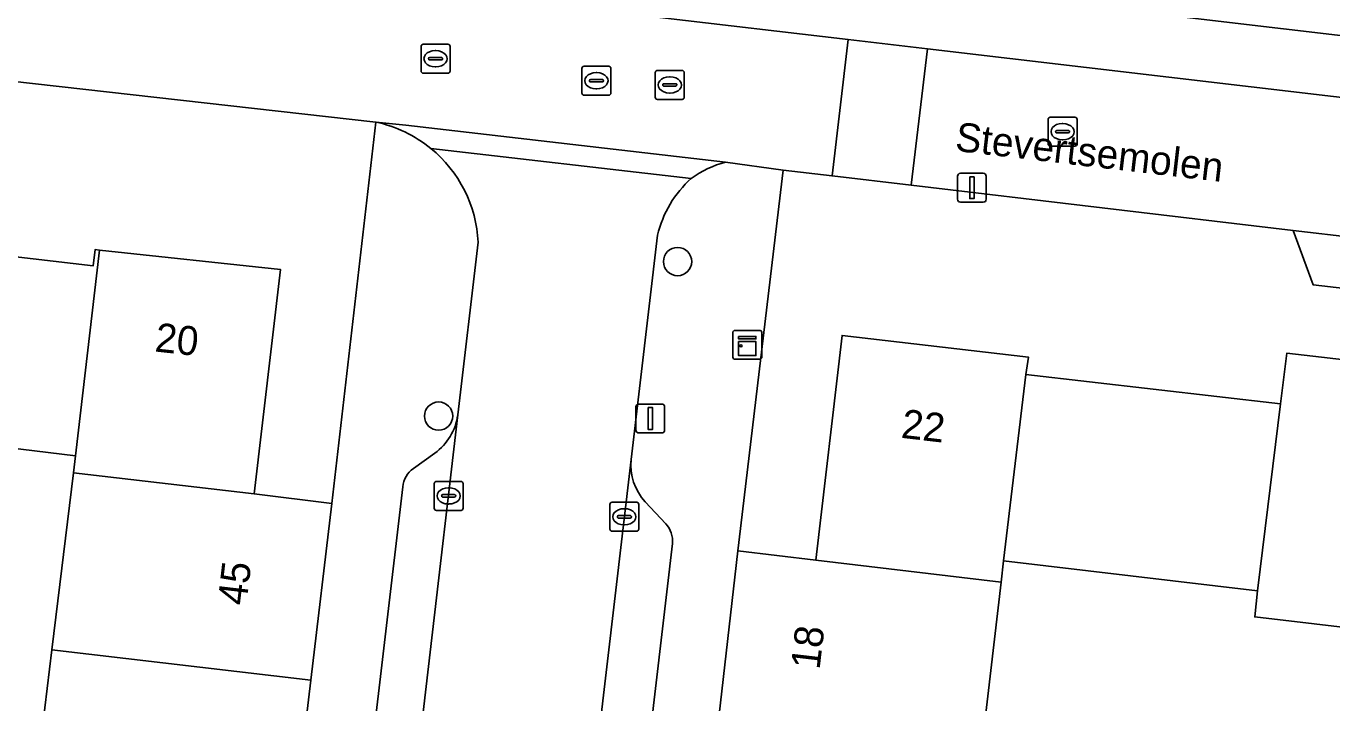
# Model space of a CAD drawing. Extents: x 161241 to 161758, y 384138 to 384885.
# Drawn here: x 161373.53 to 161418.62, y 384405.84 to 384429.23 of the extents above; entities that cross this region are included whole.
import ezdxf

# ---------------------------------------------------------------- set-up
doc = ezdxf.new("R2010")
doc.units = 0
for name, color, linetype in [('IMGEO_Boom', 7, 'Continuous'), ('IMGEO_Erf', 7, 'Continuous'), ('IMGEO_Groenvoorziening', 7, 'Continuous'), ('IMGEO_Kast', 7, 'Continuous'), ('IMGEO_Kolk', 7, 'Continuous'), ('IMGEO_Lichtmast', 7, 'Continuous'), ('IMGEO_Openbare_ruimte_label', 7, 'Continuous'), ('IMGEO_Pand', 7, 'Continuous'), ('IMGEO_Pand_nummerreeks', 7, 'Continuous'), ('IMGEO_Parkeervlak_open', 7, 'Continuous'), ('IMGEO_Rijbaan_lokaal_open', 7, 'Continuous'), ('IMGEO_Rioolput', 7, 'Continuous'), ('IMGEO_Voetpad_open', 7, 'Continuous')]:
    doc.layers.add(name, color=color, linetype=linetype)

msp = doc.modelspace()

# ---------------------------------------------------------------- linework, layer by layer
at = {"layer": 'IMGEO_Boom'}
for centre in [(161396.026, 384421.095), (161387.773, 384415.756)]:
    msp.add_circle(centre, 0.489, dxfattribs=at)
at = {"layer": 'IMGEO_Erf'}
for points in [[(161367.047, 384421.971), (161375.849, 384420.952), (161375.912, 384421.508), (161376.061, 384421.492), (161382.318, 384420.819), (161381.408, 384413.065), (161384.082, 384412.738), (161385.608, 384425.915), (161367.914, 384427.91)], [(161457.727, 384415.687), (161417.974, 384420.297), (161417.282, 384422.167), (161404.094, 384423.73), (161401.363, 384424.054), (161399.676, 384424.254), (161398.105, 384411.096), (161400.801, 384410.777), (161401.706, 384418.545), (161408.14, 384417.794), (161408.057, 384417.189), (161416.852, 384416.18), (161417.063, 384417.929), (161423.139, 384417.232)], [(161373.691, 384401.666), (161374.421, 384407.672), (161375.166, 384413.798), (161375.237, 384414.381), (161366.442, 384415.451)], [(161422.108, 384408.094), (161415.958, 384408.816), (161416.056, 384409.721), (161407.286, 384410.751), (161407.2, 384410.016), (161406.484, 384403.913), (161405.779, 384397.909), (161405.074, 384391.905), (161404.37, 384385.901), (161403.665, 384379.897), (161402.961, 384373.893), (161402.239, 384367.742), (161402.158, 384367.051), (161406.611, 384366.529), (161410.938, 384366.021), (161411.046, 384366.935), (161417.35, 384366.195), (161423.302, 384365.497)]]:
    msp.add_lwpolyline(points, dxfattribs=at)
at = {"layer": 'IMGEO_Groenvoorziening'}
msp.add_lwpolyline([(161409.377, 384462.778), (161397.9, 384454.084), (161411.738, 384445.455), (161410.62, 384434.912), (161410.092, 384429.939), (161427.439, 384427.904), (161432.833, 384473.658)], dxfattribs=at)
at = {"layer": 'IMGEO_Kast'}
for p, q in [((161398.01, 384418.718), (161398.851, 384418.718)), ((161398.851, 384418.718), (161398.01, 384418.718)), ((161397.935, 384417.793), (161397.935, 384418.634)), ((161397.935, 384418.634), (161397.935, 384417.793)), ((161398.935, 384418.643), (161398.935, 384417.802)), ((161398.935, 384417.802), (161398.935, 384418.643)), ((161398.86, 384417.718), (161398.019, 384417.718)), ((161398.019, 384417.718), (161398.86, 384417.718))]:
    msp.add_line(p, q, dxfattribs=at)
for points in [[(161398.13, 384418.508), (161398.73, 384418.508), (161398.73, 384418.423), (161398.13, 384418.423), (161398.13, 384418.508)], [(161398.13, 384418.333), (161398.73, 384418.333), (161398.73, 384417.844), (161398.13, 384417.844), (161398.13, 384418.333)]]:
    msp.add_lwpolyline(points, dxfattribs=at)
msp.add_circle((161398.214, 384418.182), 0.0377, dxfattribs=at)
for centre, start, end in [((161398.013, 384418.64), 92.4484, 184.2845), ((161398.013, 384418.64), 92.4484, 184.2845), ((161398.857, 384418.64), 2.4484, 94.2845), ((161398.857, 384418.64), 2.4484, 94.2845), ((161398.013, 384417.796), 182.4484, 274.2845), ((161398.013, 384417.796), 182.4484, 274.2845), ((161398.857, 384417.796), 272.4484, 4.2845), ((161398.857, 384417.796), 272.4484, 4.2845)]:
    msp.add_arc(centre, 0.0779, start, end, dxfattribs=at)
at = {"layer": 'IMGEO_Kolk'}
for p, q in [((161387.243, 384428.606), (161388.095, 384428.606)), ((161387.168, 384427.68), (161387.168, 384428.532)), ((161387.656, 384428.386), (161387.681, 384428.386)), ((161388.169, 384428.532), (161388.169, 384427.68)), ((161387.427, 384428.1), (161387.427, 384428.112)), ((161387.865, 384428.063), (161387.467, 384428.063)), ((161387.47, 384428.149), (161387.868, 384428.149)), ((161387.679, 384427.826), (161387.654, 384427.826)), ((161387.911, 384428.112), (161387.911, 384428.1)), ((161388.095, 384427.606), (161387.243, 384427.606)), ((161395.256, 384426.773), (161395.256, 384427.625)), ((161395.331, 384427.699), (161396.183, 384427.699)), ((161395.744, 384427.479), (161395.769, 384427.479)), ((161396.257, 384427.625), (161396.257, 384426.773)), ((161395.515, 384427.193), (161395.515, 384427.205)), ((161395.953, 384427.156), (161395.555, 384427.156)), ((161395.558, 384427.242), (161395.956, 384427.242)), ((161395.767, 384426.919), (161395.742, 384426.919)), ((161395.999, 384427.205), (161395.999, 384427.193)), ((161396.183, 384426.699), (161395.331, 384426.699)), ((161408.822, 384425.158), (161408.822, 384426.01)), ((161408.897, 384426.084), (161409.749, 384426.084)), ((161409.823, 384426.01), (161409.823, 384425.158)), ((161409.081, 384425.578), (161409.081, 384425.59)), ((161409.519, 384425.541), (161409.121, 384425.541)), ((161409.124, 384425.627), (161409.522, 384425.627)), ((161409.31, 384425.864), (161409.335, 384425.864)), ((161409.565, 384425.59), (161409.565, 384425.578)), ((161409.749, 384425.084), (161408.897, 384425.084)), ((161409.333, 384425.304), (161409.308, 384425.304)), ((161387.62, 384412.571), (161387.62, 384413.423)), ((161387.695, 384413.497), (161388.547, 384413.497)), ((161388.108, 384413.277), (161388.133, 384413.277)), ((161388.621, 384413.423), (161388.621, 384412.571)), ((161387.879, 384412.991), (161387.879, 384413.003)), ((161388.317, 384412.954), (161387.919, 384412.954)), ((161387.922, 384413.04), (161388.32, 384413.04)), ((161388.363, 384413.003), (161388.363, 384412.991)), ((161388.547, 384412.497), (161387.695, 384412.497)), ((161388.131, 384412.717), (161388.106, 384412.717)), ((161393.687, 384411.849), (161393.687, 384412.701)), ((161393.762, 384412.775), (161394.614, 384412.775)), ((161394.175, 384412.555), (161394.2, 384412.555)), ((161394.688, 384412.701), (161394.688, 384411.849)), ((161393.946, 384412.269), (161393.946, 384412.281)), ((161394.384, 384412.232), (161393.986, 384412.232)), ((161393.989, 384412.318), (161394.387, 384412.318)), ((161394.198, 384411.995), (161394.173, 384411.995)), ((161394.43, 384412.281), (161394.43, 384412.269)), ((161394.614, 384411.775), (161393.762, 384411.775))]:
    msp.add_line(p, q, dxfattribs=at)
for points in [[(161387.243, 384428.606), (161388.095, 384428.606)], [(161387.168, 384427.68), (161387.168, 384428.532)], [(161388.169, 384428.532), (161388.169, 384427.68)], [(161388.095, 384427.606), (161387.243, 384427.606)], [(161395.256, 384426.773), (161395.256, 384427.625)], [(161395.331, 384427.699), (161396.183, 384427.699)], [(161396.257, 384427.625), (161396.257, 384426.773)], [(161396.183, 384426.699), (161395.331, 384426.699)], [(161408.822, 384425.158), (161408.822, 384426.01)], [(161408.897, 384426.084), (161409.749, 384426.084)], [(161409.823, 384426.01), (161409.823, 384425.158)], [(161409.749, 384425.084), (161408.897, 384425.084)], [(161387.62, 384412.571), (161387.62, 384413.423)], [(161387.695, 384413.497), (161388.547, 384413.497)], [(161388.621, 384413.423), (161388.621, 384412.571)], [(161388.547, 384412.497), (161387.695, 384412.497)], [(161393.687, 384411.849), (161393.687, 384412.701)], [(161393.762, 384412.775), (161394.614, 384412.775)], [(161394.688, 384412.701), (161394.688, 384411.849)], [(161394.614, 384411.775), (161393.762, 384411.775)]]:
    msp.add_lwpolyline(points, dxfattribs=at)
for centre, radius, start, end in [((161387.245, 384428.53), 0.0765, 91.552, 178.448), ((161387.245, 384428.53), 0.0765, 91.552, 178.448), ((161388.093, 384428.53), 0.0765, 1.552, 88.448), ((161388.093, 384428.53), 0.0765, 1.552, 88.448), ((161387.467, 384428.109), 0.0403, 85.8775, 175.7526), ((161387.464, 384428.099), 0.0366, 178.938, 274.7102), ((161387.868, 384428.106), 0.043, 264.8664, 352.4533), ((161387.872, 384428.111), 0.0386, 1.7309, 96.639), ((161387.245, 384427.682), 0.0765, 181.552, 268.448), ((161387.245, 384427.682), 0.0765, 181.552, 268.448), ((161388.093, 384427.682), 0.0765, 271.552, 358.448), ((161388.093, 384427.682), 0.0765, 271.552, 358.448), ((161395.333, 384427.623), 0.0765, 91.552, 178.448), ((161395.333, 384427.623), 0.0765, 91.552, 178.448), ((161396.181, 384427.623), 0.0765, 1.552, 88.448), ((161396.181, 384427.623), 0.0765, 1.552, 88.448), ((161395.555, 384427.202), 0.0403, 85.8775, 175.7526), ((161395.552, 384427.192), 0.0366, 178.938, 274.7102), ((161395.956, 384427.199), 0.043, 264.8664, 352.4533), ((161395.96, 384427.204), 0.0386, 1.7309, 96.639), ((161395.333, 384426.775), 0.0765, 181.552, 268.448), ((161395.333, 384426.775), 0.0765, 181.552, 268.448), ((161396.181, 384426.775), 0.0765, 271.552, 358.448), ((161396.181, 384426.775), 0.0765, 271.552, 358.448), ((161408.899, 384426.008), 0.0765, 91.552, 178.448), ((161408.899, 384426.008), 0.0765, 91.552, 178.448), ((161409.747, 384426.008), 0.0765, 1.552, 88.448), ((161409.747, 384426.008), 0.0765, 1.552, 88.448), ((161409.121, 384425.587), 0.0403, 85.8775, 175.7526), ((161409.118, 384425.577), 0.0366, 178.938, 274.7102), ((161409.522, 384425.584), 0.043, 264.8664, 352.4533), ((161409.526, 384425.589), 0.0386, 1.7309, 96.639), ((161408.899, 384425.16), 0.0765, 181.552, 268.448), ((161408.899, 384425.16), 0.0765, 181.552, 268.448), ((161409.747, 384425.16), 0.0765, 271.552, 358.448), ((161409.747, 384425.16), 0.0765, 271.552, 358.448), ((161387.697, 384413.421), 0.0765, 91.552, 178.448), ((161387.697, 384413.421), 0.0765, 91.552, 178.448), ((161388.545, 384413.421), 0.0765, 1.552, 88.448), ((161388.545, 384413.421), 0.0765, 1.552, 88.448), ((161387.919, 384413), 0.0403, 85.8775, 175.7526), ((161387.916, 384412.99), 0.0366, 178.938, 274.7102), ((161388.32, 384412.997), 0.043, 264.8664, 352.4533), ((161388.324, 384413.002), 0.0386, 1.7309, 96.639), ((161387.697, 384412.573), 0.0765, 181.552, 268.448), ((161387.697, 384412.573), 0.0765, 181.552, 268.448), ((161388.545, 384412.573), 0.0765, 271.552, 358.448), ((161388.545, 384412.573), 0.0765, 271.552, 358.448), ((161393.764, 384412.699), 0.0765, 91.552, 178.448), ((161393.764, 384412.699), 0.0765, 91.552, 178.448), ((161394.612, 384412.699), 0.0765, 1.552, 88.448), ((161394.612, 384412.699), 0.0765, 1.552, 88.448), ((161393.986, 384412.278), 0.0403, 85.8775, 175.7526), ((161393.983, 384412.268), 0.0366, 178.938, 274.7102), ((161394.387, 384412.275), 0.043, 264.8664, 352.4533), ((161394.391, 384412.28), 0.0386, 1.7309, 96.639), ((161393.764, 384411.851), 0.0765, 181.552, 268.448), ((161393.764, 384411.851), 0.0765, 181.552, 268.448), ((161394.612, 384411.851), 0.0765, 271.552, 358.448), ((161394.612, 384411.851), 0.0765, 271.552, 358.448)]:
    msp.add_arc(centre, radius, start, end, dxfattribs=at)
for centre, major_axis, ratio, start_param, end_param in [((161387.655, 384428.106), (-0.387, 0.002), 0.722429, 4.712389, 7.853982), ((161387.68, 384428.106), (-0.39, 0.002), 0.717154, 1.570796, 4.712389), ((161395.743, 384427.199), (-0.387, 0.002), 0.722429, 4.712389, 7.853982), ((161395.768, 384427.199), (-0.39, 0.002), 0.717154, 1.570796, 4.712389), ((161409.309, 384425.584), (-0.387, 0.002), 0.722429, 4.712389, 7.853982), ((161409.334, 384425.584), (-0.39, 0.002), 0.717154, 1.570796, 4.712389), ((161388.107, 384412.997), (-0.387, 0.002), 0.722429, 4.712389, 7.853982), ((161388.132, 384412.997), (-0.39, 0.002), 0.717154, 1.570796, 4.712389), ((161394.174, 384412.275), (-0.387, 0.002), 0.722429, 4.712389, 7.853982), ((161394.199, 384412.275), (-0.39, 0.002), 0.717154, 1.570796, 4.712389)]:
    msp.add_ellipse(centre, major_axis=major_axis, ratio=ratio, start_param=start_param, end_param=end_param, dxfattribs=at)
at = {"layer": 'IMGEO_Lichtmast'}
for p, q in [((161405.794, 384424.147), (161406.584, 384424.147)), ((161406.584, 384424.147), (161405.794, 384424.147)), ((161405.694, 384423.247), (161405.694, 384424.047)), ((161405.694, 384424.047), (161405.694, 384423.247)), ((161406.684, 384424.047), (161406.684, 384423.247)), ((161406.684, 384423.247), (161406.684, 384424.047)), ((161406.584, 384423.147), (161405.794, 384423.147)), ((161405.794, 384423.147), (161406.584, 384423.147)), ((161394.59, 384415.272), (161394.59, 384416.072)), ((161394.59, 384416.072), (161394.59, 384415.272)), ((161394.69, 384416.172), (161395.48, 384416.172)), ((161395.48, 384416.172), (161394.69, 384416.172)), ((161395.58, 384416.072), (161395.58, 384415.272)), ((161395.58, 384415.272), (161395.58, 384416.072)), ((161395.48, 384415.172), (161394.69, 384415.172)), ((161394.69, 384415.172), (161395.48, 384415.172))]:
    msp.add_line(p, q, dxfattribs=at)
for points in [[(161406.114, 384424.022), (161406.264, 384424.022), (161406.264, 384423.272), (161406.114, 384423.272), (161406.114, 384424.022)], [(161395.01, 384416.047), (161395.16, 384416.047), (161395.16, 384415.297), (161395.01, 384415.297), (161395.01, 384416.047)]]:
    msp.add_lwpolyline(points, dxfattribs=at)
for centre, start, end in [((161405.794, 384424.047), 90, 180), ((161405.794, 384424.047), 90, 180), ((161406.584, 384424.047), 0, 90), ((161406.584, 384424.047), 360, 90), ((161405.794, 384423.247), 180, 270), ((161405.794, 384423.247), 180, 270), ((161406.584, 384423.247), 270, 0), ((161406.584, 384423.247), 270, 0), ((161394.69, 384416.072), 90, 180), ((161394.69, 384416.072), 90, 180), ((161395.48, 384416.072), 0, 90), ((161395.48, 384416.072), 360, 90), ((161394.69, 384415.272), 180, 270), ((161394.69, 384415.272), 180, 270), ((161395.48, 384415.272), 270, 0), ((161395.48, 384415.272), 270, 0)]:
    msp.add_arc(centre, 0.1, start, end, dxfattribs=at)
at = {"layer": 'IMGEO_Pand'}
for points in [[(161375.237, 384414.381), (161376.061, 384421.492), (161375.912, 384421.508), (161375.849, 384420.952), (161367.047, 384421.971), (161366.294, 384415.469), (161366.442, 384415.451)], [(161382.318, 384420.819), (161376.061, 384421.492), (161375.237, 384414.381), (161375.166, 384413.798), (161381.408, 384413.065)], [(161400.801, 384410.777), (161407.2, 384410.016), (161407.286, 384410.751), (161408.057, 384417.189), (161408.14, 384417.794), (161401.706, 384418.545)], [(161416.056, 384409.721), (161415.958, 384408.816), (161422.108, 384408.094), (161423.139, 384417.232), (161417.063, 384417.929), (161416.852, 384416.18)], [(161408.057, 384417.189), (161407.286, 384410.751), (161416.056, 384409.721), (161416.852, 384416.18)], [(161384.082, 384412.738), (161381.408, 384413.065), (161375.166, 384413.798), (161374.421, 384407.672), (161383.357, 384406.631)], [(161397.406, 384404.939), (161406.484, 384403.913), (161407.2, 384410.016), (161400.801, 384410.777), (161398.105, 384411.096)], [(161382.874, 384400.88), (161382.676, 384400.9), (161383.357, 384406.631), (161374.421, 384407.672), (161373.691, 384401.666), (161382.786, 384400.607)]]:
    msp.add_lwpolyline(points, close=True, dxfattribs=at)
at = {"layer": 'IMGEO_Parkeervlak_open'}
msp.add_lwpolyline([(161417.282, 384422.167), (161417.974, 384420.297), (161457.727, 384415.687), (161459.347, 384417.271), (161454.814, 384417.799), (161452.092, 384418.115)], close=True, dxfattribs=at)
for points in [[(161382.703, 384366.584), (161388.436, 384415.795)], [(161387.639, 384414.474), (161386.903, 384413.941)], [(161394.42, 384414.251), (161388.778, 384366.166)], [(161386.534, 384413.313), (161381.37, 384369.393)], [(161395.619, 384412.033), (161394.905, 384412.788)], [(161390.818, 384368.412), (161395.846, 384411.348)]]:
    msp.add_lwpolyline(points, dxfattribs=at)
for centre, radius, start, end in [((161386.485, 384416.071), 1.971, 305.8502, 351.942), ((161396.33, 384414.072), 1.918, 174.6559, 222.0259), ((161387.427, 384413.211), 0.899, 125.6584, 173.4663), ((161394.995, 384411.446), 0.857, 353.426, 43.243)]:
    msp.add_arc(centre, radius, start, end, dxfattribs=at)
at = {"layer": 'IMGEO_Rijbaan_lokaal_open'}
for points in [[(161346.013, 384430.497), (161367.914, 384427.91), (161385.608, 384425.915), (161386.646, 384425.81), (161397.686, 384424.536), (161399.676, 384424.254), (161401.363, 384424.054), (161401.922, 384428.768), (161382.402, 384431.06), (161336.257, 384436.376)], [(161386.646, 384425.81), (161385.608, 384425.915)], [(161397.686, 384424.536), (161386.646, 384425.81)], [(161387.504, 384425.007), (161396.501, 384423.968)], [(161396.501, 384423.968), (161387.504, 384425.007)], [(161394.42, 384414.251), (161395.335, 384422.009)], [(161389.139, 384421.761), (161388.436, 384415.795), (161382.703, 384366.584), (161388.754, 384365.965), (161388.778, 384366.166), (161394.42, 384414.251)]]:
    msp.add_lwpolyline(points, dxfattribs=at)
for points in [[(161401.922, 384428.768), (161401.363, 384424.054), (161404.094, 384423.73), (161404.653, 384428.447)], [(161417.282, 384422.167), (161452.092, 384418.115), (161452.639, 384422.825), (161443.686, 384423.864), (161404.653, 384428.447), (161404.094, 384423.73)]]:
    msp.add_lwpolyline(points, close=True, dxfattribs=at)
for centre, radius, start, end in [((161384.678, 384421.539), 4.473, 50.8205, 77.9997), ((161384.679, 384421.549), 4.465, 2.7202, 50.7483), ((161398.643, 384421.019), 3.645, 105.2232, 125.9959), ((161399.039, 384421.131), 3.807, 131.8146, 166.6631)]:
    msp.add_arc(centre, radius, start, end, dxfattribs=at)
at = {"layer": 'IMGEO_Rioolput'}
for p, q in [((161392.723, 384426.919), (161392.723, 384427.771)), ((161392.798, 384427.845), (161393.65, 384427.845)), ((161393.724, 384427.771), (161393.724, 384426.919)), ((161392.982, 384427.339), (161392.982, 384427.351)), ((161393.42, 384427.302), (161393.022, 384427.302)), ((161393.025, 384427.388), (161393.423, 384427.388)), ((161393.211, 384427.625), (161393.236, 384427.625)), ((161393.466, 384427.351), (161393.466, 384427.339)), ((161393.65, 384426.845), (161392.798, 384426.845)), ((161393.234, 384427.065), (161393.209, 384427.065))]:
    msp.add_line(p, q, dxfattribs=at)
for points in [[(161392.723, 384426.919), (161392.723, 384427.771)], [(161392.798, 384427.845), (161393.65, 384427.845)], [(161393.724, 384427.771), (161393.724, 384426.919)], [(161393.65, 384426.845), (161392.798, 384426.845)]]:
    msp.add_lwpolyline(points, dxfattribs=at)
for centre, radius, start, end in [((161392.8, 384427.769), 0.0765, 91.552, 178.448), ((161392.8, 384427.769), 0.0765, 91.552, 178.448), ((161393.648, 384427.769), 0.0765, 1.552, 88.448), ((161393.648, 384427.769), 0.0765, 1.552, 88.448), ((161393.022, 384427.348), 0.0403, 85.8775, 175.7526), ((161393.019, 384427.338), 0.0366, 178.938, 274.7102), ((161393.423, 384427.345), 0.043, 264.8664, 352.4533), ((161393.427, 384427.35), 0.0386, 1.7309, 96.639), ((161392.8, 384426.921), 0.0765, 181.552, 268.448), ((161392.8, 384426.921), 0.0765, 181.552, 268.448), ((161393.648, 384426.921), 0.0765, 271.552, 358.448), ((161393.648, 384426.921), 0.0765, 271.552, 358.448)]:
    msp.add_arc(centre, radius, start, end, dxfattribs=at)
for centre, major_axis, ratio, start_param, end_param in [((161393.21, 384427.345), (-0.387, 0.002), 0.722429, 4.712389, 7.853982), ((161393.235, 384427.345), (-0.39, 0.002), 0.717154, 1.570796, 4.712389)]:
    msp.add_ellipse(centre, major_axis=major_axis, ratio=ratio, start_param=start_param, end_param=end_param, dxfattribs=at)
at = {"layer": 'IMGEO_Voetpad_open'}
msp.add_lwpolyline([(161427.439, 384427.904), (161410.092, 384429.939), (161407.225, 384430.276), (161404.443, 384430.602), (161399.514, 384431.19), (161393.511, 384431.885), (161387.488, 384432.576), (161336.535, 384438.485), (161336.257, 384436.376), (161382.402, 384431.06), (161401.922, 384428.768), (161404.653, 384428.447), (161443.686, 384423.864), (161452.639, 384422.825), (161455.361, 384422.51), (161500, 384417.331), (161516.896, 384415.376), (161517.124, 384417.504), (161500, 384419.47), (161446.947, 384425.581), (161440.852, 384426.331)], close=True, dxfattribs=at)
for points in [[(161385.608, 384425.915), (161384.082, 384412.738), (161383.357, 384406.631), (161382.676, 384400.9), (161382.874, 384400.88), (161382.786, 384400.607), (161382.68, 384400.278), (161382.051, 384394.962), (161382.312, 384394.905), (161382.283, 384394.576), (161382.258, 384394.289), (161381.966, 384394.286), (161381.358, 384389.015), (161381.625, 384388.946), (161381.595, 384388.565), (161381.576, 384388.326), (161381.287, 384388.32), (161380.642, 384382.887), (161380.741, 384382.836), (161380.717, 384382.578), (161380.682, 384382.194), (161379.959, 384376.576), (161379.174, 384370.478), (161378.268, 384362.293)], [(161393.196, 384368.833), (161393.932, 384374.913), (161394.628, 384380.668), (161394.479, 384380.669), (161394.513, 384380.931), (161395.281, 384386.776), (161395.038, 384386.784), (161395.057, 384386.953), (161395.109, 384387.422), (161395.366, 384387.436), (161395.992, 384392.683), (161395.682, 384392.718), (161395.717, 384392.962), (161395.773, 384393.351), (161396.058, 384393.363), (161396.607, 384398.945), (161396.639, 384399.27), (161396.761, 384399.263), (161397.406, 384404.939), (161398.105, 384411.096), (161399.676, 384424.254), (161397.686, 384424.536)], [(161395.335, 384422.009), (161394.42, 384414.251)], [(161388.436, 384415.795), (161389.139, 384421.761)], [(161386.903, 384413.941), (161387.639, 384414.474)], [(161381.37, 384369.393), (161386.534, 384413.313)], [(161394.905, 384412.788), (161395.619, 384412.033)], [(161395.846, 384411.348), (161390.818, 384368.412)]]:
    msp.add_lwpolyline(points, dxfattribs=at)
for centre, radius, start, end in [((161384.678, 384421.539), 4.473, 50.8205, 77.9997), ((161384.679, 384421.549), 4.465, 2.7202, 50.7483), ((161398.643, 384421.019), 3.645, 105.2232, 125.9959), ((161399.039, 384421.131), 3.807, 131.8146, 166.6631), ((161386.485, 384416.071), 1.971, 305.8502, 351.942), ((161396.33, 384414.072), 1.918, 174.6559, 222.0259), ((161387.427, 384413.211), 0.899, 125.6584, 173.4663), ((161394.995, 384411.446), 0.857, 353.426, 43.243)]:
    msp.add_arc(centre, radius, start, end, dxfattribs=at)

# ---------------------------------------------------------------- texts
at = {"layer": 'IMGEO_Openbare_ruimte_label'}
msp.add_text('Stevertsemolen', height=1, rotation=353.337, dxfattribs=at).set_placement((161405.583, 384424.925))
at = {"layer": 'IMGEO_Pand_nummerreeks'}
for s, rotation, p in [('20', 353.8611, (161377.946, 384417.99)), ('22', 353.3424, (161403.719, 384415.008)), ('45', 83.3755, (161381.133, 384409.189)), ('18', 83.3746, (161400.928, 384406.972))]:
    msp.add_text(s, height=1, rotation=rotation, dxfattribs=at).set_placement(p)

doc.saveas('drawing.dxf')
